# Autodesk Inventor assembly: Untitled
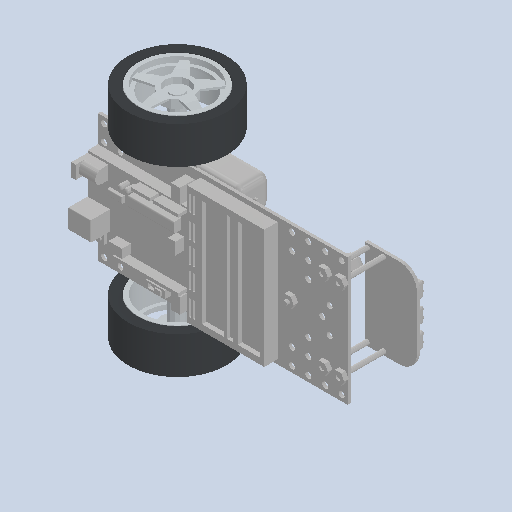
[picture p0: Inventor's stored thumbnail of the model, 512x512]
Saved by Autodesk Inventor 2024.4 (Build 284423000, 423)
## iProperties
Created: 2026-02
Part Number: Untitled
Document SubType Name: Assembly
Designer: AdminForWorker
Title: Untitled v2
Author: AdminForWorker
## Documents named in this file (8)
- c:\worker\convert-fusion-r06-cosv3\tmp\job-1\4\temp\files\9e11f7b7-efdd-402c-8b6c-6dd3a004713c\15b00054-21c6-4145-835e-c1cfcd504537.iam
- c:\worker\convert-fusion-r06-cosv3\tmp\job-1\4\temp\files\9e11f7b7-efdd-402c-8b6c-6dd3a004713c\BUGGY TOPSIDE v1.ipt
- c:\worker\convert-fusion-r06-cosv3\tmp\job-1\4\temp\files\9e11f7b7-efdd-402c-8b6c-6dd3a004713c\MOTOR v1.ipt
- c:\worker\convert-fusion-r06-cosv3\tmp\job-1\4\temp\files\9e11f7b7-efdd-402c-8b6c-6dd3a004713c\line follower v1.ipt
- c:\worker\convert-fusion-r06-cosv3\tmp\job-1\4\temp\files\9e11f7b7-efdd-402c-8b6c-6dd3a004713c\NUT v1.ipt
- c:\worker\convert-fusion-r06-cosv3\tmp\job-1\4\temp\files\9e11f7b7-efdd-402c-8b6c-6dd3a004713c\nub v1.ipt
- c:\worker\convert-fusion-r06-cosv3\tmp\job-1\4\temp\files\9e11f7b7-efdd-402c-8b6c-6dd3a004713c\wheel-group2 v1.ipt
- c:\worker\convert-fusion-r06-cosv3\tmp\job-1\4\temp\files\9e11f7b7-efdd-402c-8b6c-6dd3a004713c\battery model two v1.ipt
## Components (13 placed, 7 different names)
1. BUGGY TOPSIDE v1:1
2. MOTOR v1:1
3. MOTOR v1:2
4. line follower v1:1
5. NUT v1:1
6. NUT v1:2
7. NUT v1:3
8. NUT v1:4
9. nub v1:1
10. NUT v1:5
11. wheel-group2 v1:1
12. wheel-group2 v1:2
13. battery model two v1:1
